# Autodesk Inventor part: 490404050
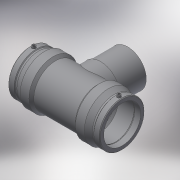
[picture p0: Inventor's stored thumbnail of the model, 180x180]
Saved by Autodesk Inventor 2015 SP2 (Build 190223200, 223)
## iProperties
Created: 2017-06
Part Number: 490404050
Material: Generic
Description: PLASSON TEE 50-50-50
Document SubType Name: Modeling
Designer: KIM
Mass: 259.71 g
Surface Area: 749.667 cm^2
Volume: 259.71 cm^3
Density: 1 g/cm^3
Appearance: Default
Author: KIM
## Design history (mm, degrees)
derived "490404.ipt"
feature "Solid1::490404.ipt"
tag "TaggingFeature1"
body "Solid1"
other parameters: "d0" = 139, "d2" = 68, "d3" = 48, "d4" = 34.75, "d5" = 61.2, "d6" = 47.5, "d8" = 168 deg, "d10" = 19.2, "d11" = 6.4, "d13" = 139, "d14" = 17.6296, "d17" = 45, "d19" = 3.52592, "d20" = 168 deg, "d22" = 63.24, "d23" = 68, "d24" = 61.3428, "d25" = 135 deg, "d26" = 97.3, "d27" = 135 deg, "d29" = 52, "d30" = 15, "d31" = 55.6, "d34" = 5 deg, "d35" = 15, "d39" = 5 deg, "d40" = 9.6, "d41" = 4.8, "d42" = 6, "d43" = 0, "d45" = 4, "d46" = 14, "d47" = 0, "d48" = -102, "d51" = 0, "d54" = 0, "d55" = 61.2, "d56" = 68, "d57" = 48.65, "d58" = 135 deg, "d59" = 48, "d60" = 48, "d61" = 135 deg, "d62" = 102, "d72" = 63.245, "d73" = 31.6225, "d74" = -102, "d75" = 52.5, "d77" = 0, "d80" = 0, "d82" = 68, "d83" = 0, "d84" = 3, "d85" = 0, "d86" = 3, "d87" = 0, "d88" = 13.92, "d89" = 3.48, "d90" = 13.92, "L_" = 139, "L_1" = 48, "D_" = 68, "A_" = 52, "d_2" = 12, "H_" = 102
